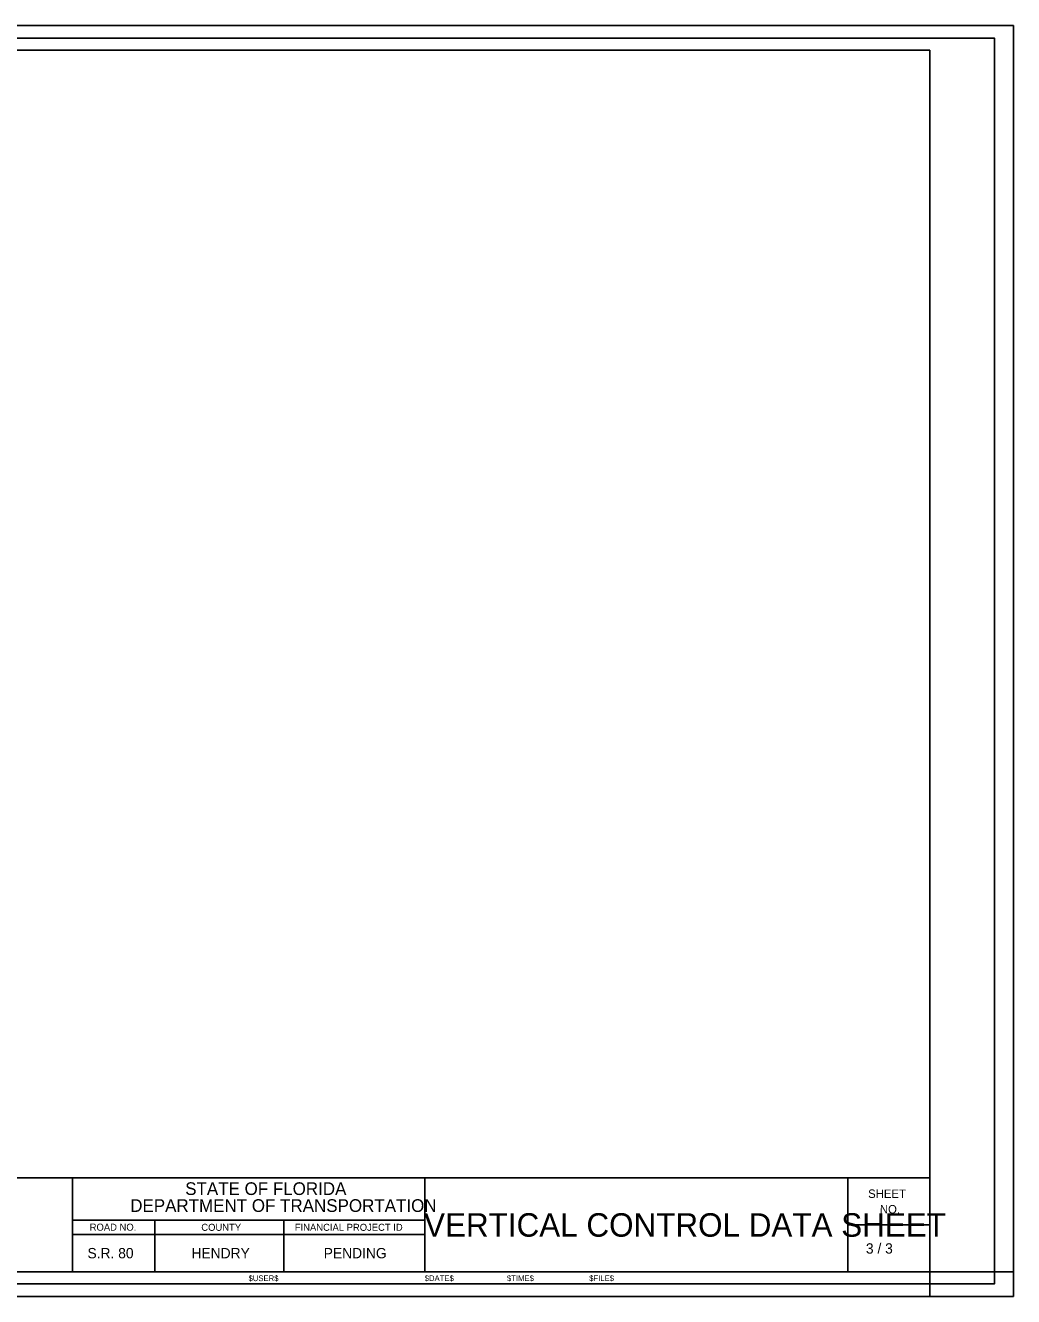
# Model space of a CAD drawing. Extents: x 90.1 to 106.9, y 42.9 to 53.7.
# Drawn here: x 98.48 to 106.9, y 42.85 to 53.67 of the extents above; entities that cross this region are included whole.
import ezdxf

# ---------------------------------------------------------------- set-up
doc = ezdxf.new("R2010")
doc.units = 0
for name, color, linetype in [('AdhocPoint_dp', 7, 'Continuous'), ('ConstLines', 7, 'Continuous'), ('PlotBorder_dp', 7, 'Continuous'), ('SheetBorder_dp', 7, 'Continuous'), ('SheetLines_dp', 7, 'Continuous'), ('TextMinor', 7, 'Continuous'), ('TextMisc', 7, 'Continuous'), ('TextShtNo', 7, 'Continuous')]:
    doc.layers.add(name, color=color, linetype=linetype)

msp = doc.modelspace()

# ---------------------------------------------------------------- linework, layer by layer
at = {"layer": 'AdhocPoint_dp'}
msp.add_line((106.733, 42.961), (106.733, 42.961), dxfattribs=at)
at = {"layer": 'ConstLines'}
for p, q in [((106.895, 53.671), (90.07, 53.671)), ((106.895, 53.671), (106.895, 42.851)), ((106.183, 43.061), (106.183, 42.851)), ((106.183, 43.061), (106.895, 43.061)), ((90.07, 42.852), (106.895, 42.851))]:
    msp.add_line(p, q, dxfattribs=at)
at = {"layer": 'PlotBorder_dp'}
msp.add_lwpolyline([(90.233, 42.961), (106.733, 42.961), (106.733, 53.561), (90.233, 53.561)], close=True, dxfattribs=at)
at = {"layer": 'SheetBorder_dp'}
for p, q in [((90.783, 53.461), (106.183, 53.461)), ((106.183, 53.461), (106.183, 43.061)), ((90.783, 43.861), (106.183, 43.861)), ((90.783, 43.061), (106.183, 43.061))]:
    msp.add_line(p, q, dxfattribs=at)
at = {"layer": 'SheetLines_dp'}
for p, q in [((98.883, 43.861), (98.883, 43.061)), ((101.883, 43.061), (101.883, 43.861)), ((105.483, 43.061), (105.483, 43.861)), ((98.883, 43.501), (101.883, 43.501)), ((99.583, 43.501), (99.583, 43.061)), ((100.683, 43.501), (100.683, 43.061)), ((105.483, 43.461), (106.183, 43.461)), ((98.883, 43.381), (101.883, 43.381))]:
    msp.add_line(p, q, dxfattribs=at)

# ---------------------------------------------------------------- texts
at = {"layer": 'TextMinor'}
for s, p in [('$USER$', (100.382, 42.983)), ('$DATE$', (101.882, 42.983)), ('$TIME$', (102.582, 42.983)), ('$FILE$', (103.282, 42.983))]:
    msp.add_text(s, height=0.049, dxfattribs=at).set_placement(p)
at = {"layer": 'TextMisc'}
for s, height, p in [('STATE OF FLORIDA', 0.108, (99.843, 43.716)), ('DEPARTMENT OF TRANSPORTATION', 0.108, (99.375, 43.572)), (' VERTICAL CONTROL DATA SHEET  ', 0.2, (101.802, 43.361)), ('ROAD NO.', 0.06, (99.03, 43.412)), ('COUNTY', 0.06, (99.98, 43.411)), ('FINANCIAL PROJECT ID', 0.06, (100.776, 43.411)), ('S.R. 80', 0.088, (99.011, 43.177)), ('HENDRY', 0.088, (99.896, 43.177)), ('PENDING', 0.088, (101.022, 43.177))]:
    msp.add_text(s, height=height, dxfattribs=at).set_placement(p)
for s, p in [('SHEET', (105.657, 43.691)), ('NO.', (105.757, 43.559))]:
    msp.add_text(s, height=0.072, rotation=359.8607, dxfattribs=at).set_placement(p)
at = {"layer": 'TextShtNo'}
msp.add_text('3 / 3', height=0.088, dxfattribs=at).set_placement((105.638, 43.217))

doc.saveas('drawing.dxf')
